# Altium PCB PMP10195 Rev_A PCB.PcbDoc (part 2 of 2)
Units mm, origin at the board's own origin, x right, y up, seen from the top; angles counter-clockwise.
Board outline 60.32 x 50 mm, 4 copper layers (Top Layer, Signal Layer 1, Signal Layer 2, Bottom Layer), stack 2.028 mm thick; 90 components, 50 nets, 184 pads, 78 vias.
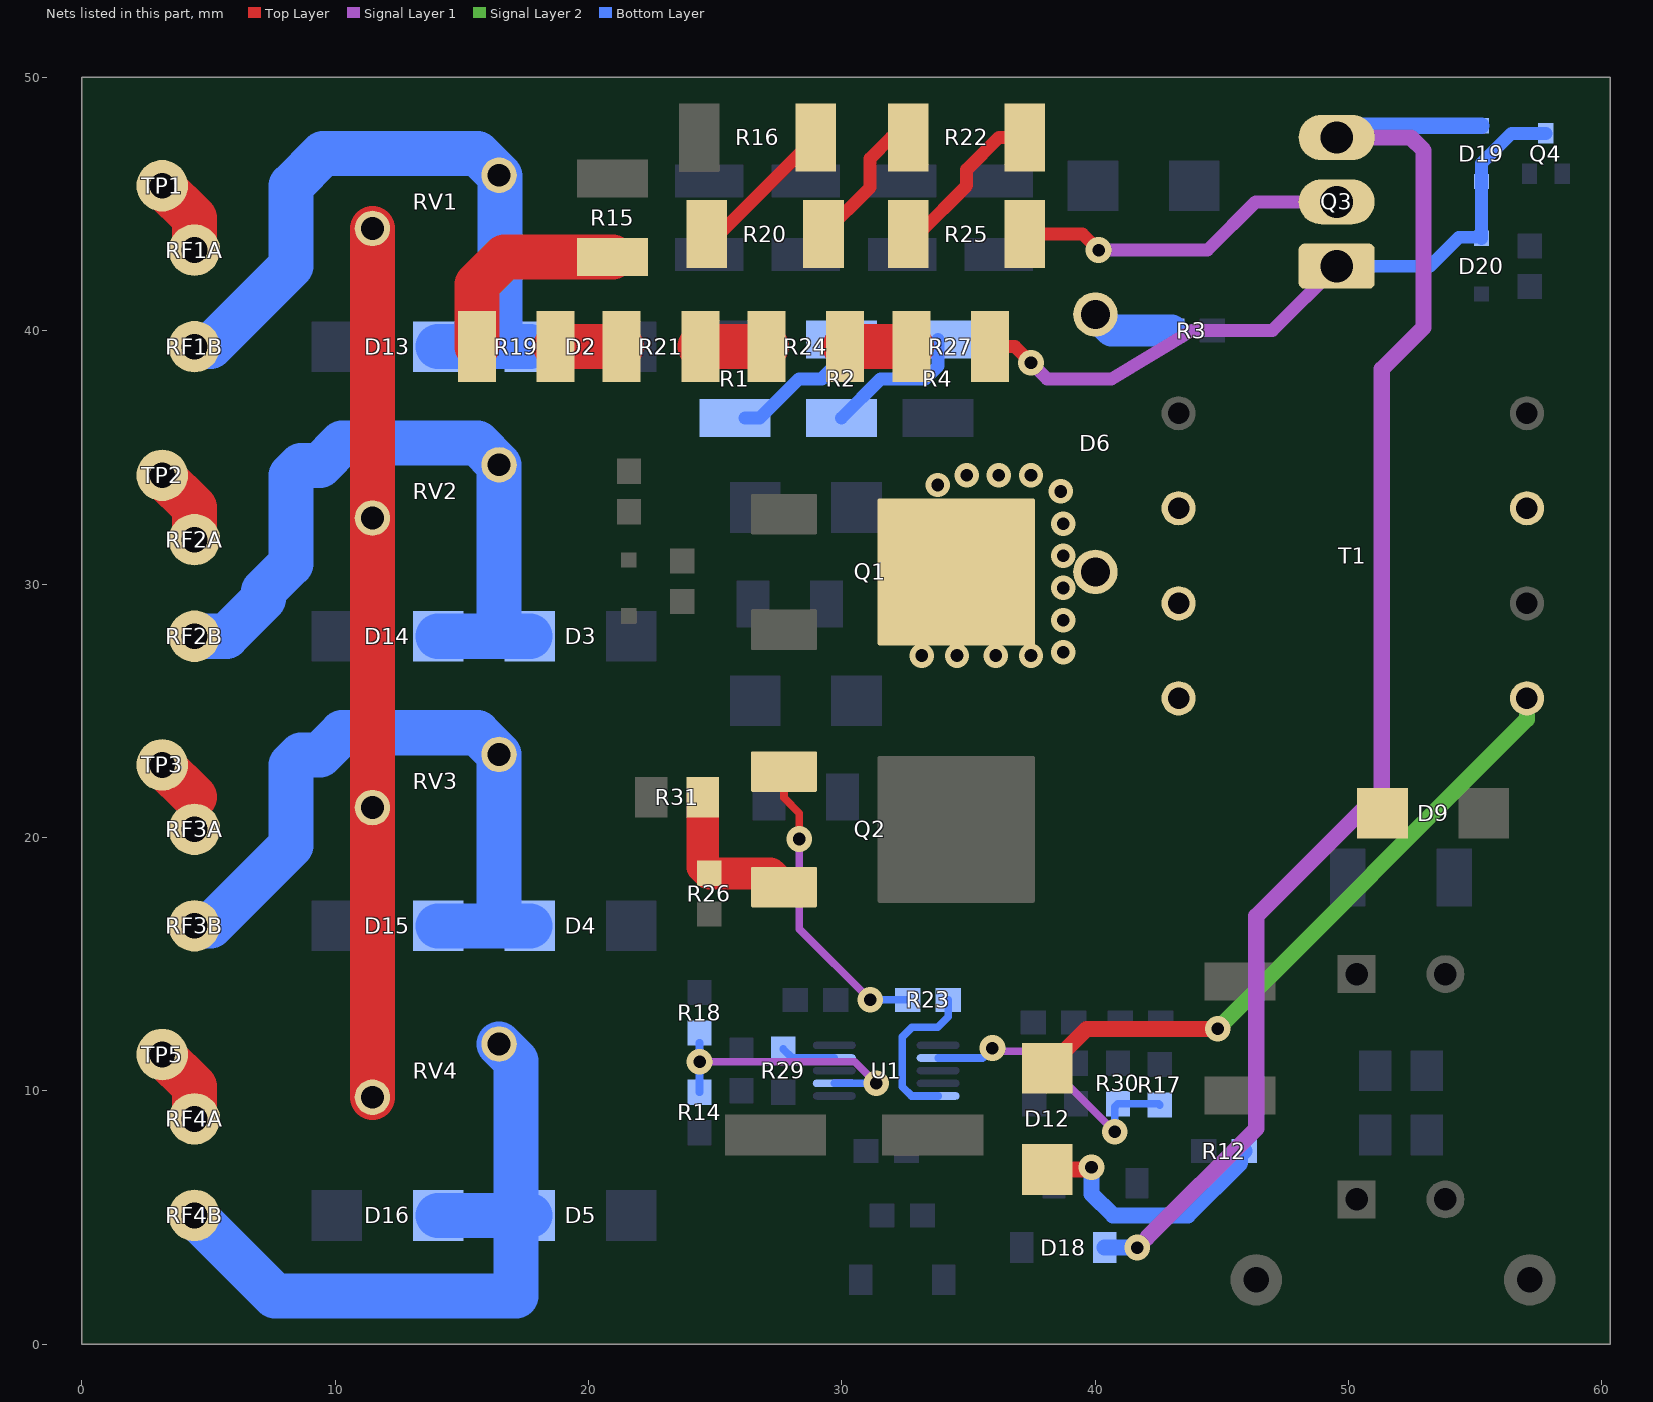
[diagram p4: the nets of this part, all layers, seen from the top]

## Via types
v1: diameter 0.965, hole 0.5, Top Layer to Bottom Layer, 51 vias
v2: diameter 1.016, hole 0.5, Top Layer to Bottom Layer, 19 vias
v3: diameter 1.27, hole 0.711, Top Layer to Bottom Layer, 8 vias

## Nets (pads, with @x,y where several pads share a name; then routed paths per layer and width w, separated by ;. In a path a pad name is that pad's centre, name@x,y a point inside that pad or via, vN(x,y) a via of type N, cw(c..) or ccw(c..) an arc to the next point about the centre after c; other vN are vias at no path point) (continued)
NetD2_2: D2.2 D13.1 RF1B.1 RV1.1 | length 27.8
  Bottom Layer w1.778: RF1B.1@4.445,39.37 5.08,39.37 8.255,42.545 8.255,45.72 9.525,46.99 15.615,46.99 RV1.1@16.47,46.135 16.51,46.095 16.51,39.37 ; D13.1@14.065,39.37 16.51,39.37 ; D2.2@17.685,39.37 16.51,39.37
NetD3_2: D3.2 D14.1 RF2B.1 RV2.1 | length 28.2
  Bottom Layer w1.778: RF2B.1@4.445,27.94 5.715,27.94 7.176,29.401 7.176,29.722 8.255,30.801 8.255,34.29 8.652,34.687 9.406,34.687 10.279,35.56 15.615,35.56 RV2.1@16.47,34.705 16.47,27.98 16.51,27.94 ; D14.1@14.065,27.94 16.51,27.94 ; D3.2@17.685,27.94 16.51,27.94
NetD4_2: D4.2 D15.1 RF3B.1 RV3.1 | length 27.8
  Bottom Layer w1.778: RF3B.1@4.445,16.51 5.08,16.51 8.255,19.685 8.255,22.86 8.652,23.257 9.406,23.257 10.279,24.13 15.615,24.13 RV3.1@16.47,23.275 16.47,16.55 16.51,16.51 ; D15.1@14.065,16.51 16.51,16.51 ; D4.2@17.685,16.51 16.51,16.51
NetD5_2: D5.2 D16.1 RF4B.1 RV4.1 | length 27.9
  Bottom Layer w1.778: RF4B.1@4.445,5.08 7.62,1.905 17.145,1.905 D5.2@17.145,5.08 ; D16.1@14.065,5.08 D5.2@17.145,5.08 ; RV4.1@16.47,11.845 17.145,11.17 D5.2@17.145,5.08 ; D5.2@17.685,5.08 D5.2@17.145,5.08
NetD6_1: D6.1 R3.1 | length 3.3
  Bottom Layer w1.27: D6.1@40.005,40.64 40.64,40.005 R3.1@43.015,40.005
NetD6_2: D6.2 Q1.4 T1.2 T1.3 T1.4
  other v1: 33.147,27.178 34.544,27.178 36.068,27.178 37.465,27.178 38.735,27.305 38.735,28.575 38.735,29.845 38.735,31.115 38.735,32.385 38.633,33.655 33.782,33.909 34.925,34.29 36.195,34.29 37.465,34.29
NetD9_2: D9.2 T1.7
NetD12_1: D12.1 R12.1 | length 10.5
  Top Layer w0.635: D12.1@38.1,6.89 39.755,6.89 v2(39.85,6.985)
  Bottom Layer w0.635: v2(39.85,6.985) 39.85,5.933 40.703,5.08 43.66,5.08 45.72,7.14 45.72,7.455 R12.1@45.885,7.62
NetD12_2: D12.2 T1.5 | length 25.5
  Top Layer w0.635: D12.2@38.1,10.89 39.656,12.446 v2(44.831,12.446)
  Signal Layer 2 w0.635: v2(44.831,12.446) 57.04,24.655 T1.5@57.04,25.49
NetD18_2: D18.2 D19.2 Q3.3 | length 58.3
  Signal Layer 1 w0.635: 42.037,4.191 46.355,8.509 46.355,16.891 51.308,21.844 51.308,38.481 52.959,40.132 52.959,47.117 52.451,47.625 Q3.3@49.53,47.625
  Bottom Layer w0.635: D18.2@40.372,3.81 v2(41.656,3.81) ; Q3.3@49.53,47.625 49.995,48.09 D19.2@55.245,48.09
NetD19_1: D19.1 D20.1 Q3.1 Q4.3 R27.1 | length 28
  Top Layer w0.508: R27.1@35.84,39.37 36.83,39.37 v2(37.465,38.735)
  Signal Layer 1 w0.508: v2(37.465,38.735) 38.1,38.1 40.64,38.1 43.815,40.005 46.99,40.005 Q3.1@49.53,42.545
  Bottom Layer w0.508: Q3.1@49.53,42.545 53.213,42.545 54.356,43.688 55.202,43.688 D20.1@55.245,43.645 D19.1@55.245,45.89 55.245,46.609 56.426,47.79 Q4.3@57.785,47.79
NetQ2_1: Q2.1 R23.2 | length 11.9
  Top Layer w0.305: Q2.1@27.715,22.6 27.715,21.561 28.321,20.955 v2(28.321,19.939)
  Signal Layer 1 w0.305: v2(28.321,19.939) 28.321,16.383 v2(31.115,13.589)
  Bottom Layer w0.305: v2(31.115,13.589) R23.2@32.601,13.589
NetQ2_3: Q2.3 R26.1 R31.2 | length 6.3
  Top Layer w1.27: R31.2@24.511,21.59 24.511,18.834 R26.1@24.765,18.58 27.175,18.58 Q2.3@27.715,18.04
NetQ3_2: Q3.2 R25.1 | length 13.4
  Top Layer w0.508: R25.1@37.225,43.815 39.497,43.815 v2(40.132,43.18)
  Signal Layer 1 w0.508: v2(40.132,43.18) 44.43,43.18 46.335,45.085 Q3.2@49.53,45.085
NetR1_1: R1.1 R2.2 | length 5.7
  Bottom Layer w0.508: R1.1@26.17,36.55 26.76,36.55 28.31,38.1 29.21,38.1 29.966,38.856 30.102,38.856 29.98,38.978 R2.2@29.98,39.65
NetR2_1: R2.1 R4.2 | length 5.7
  Bottom Layer w0.508: R2.1@29.98,36.55 31.53,38.1 33.29,38.1 33.79,38.6 R4.2@33.79,39.65
NetR14_1: R14.1 R18.2 U1.7 | length 10.9
  Signal Layer 1 w0.305: v2(24.384,11.15) 30.506,11.15 v2(31.361,10.295)
  Bottom Layer w0.305: R14.1@24.384,9.944 v2(24.384,11.15) R18.2@24.384,11.9 ; U1.7@29.7,10.295 v2(31.361,10.295)
NetR15_1: R15.1 R19.2 | length 8.3
  Top Layer w1.778: R19.2@15.595,39.37 15.595,41.818 16.678,42.9 R15.1@20.955,42.9
NetR16_1: R16.1 R20.2 | length 5.9
  Top Layer w0.508: R20.2@24.675,43.815 25.16,43.815 R16.1@28.97,47.625
NetR17_1: R17.1 R30.2 U1.2 | length 11.5
  Signal Layer 1 w0.305: v2(35.941,11.684) 35.941,11.557 37.592,11.557 v2(40.767,8.382)
  Bottom Layer w0.305: U1.2@33.8,11.295 35.552,11.295 35.814,11.557 35.941,11.557 v2(35.941,11.684) ; v2(40.767,8.382) 40.767,9.36 R30.2@40.894,9.487 42.496,9.487 R17.1@42.545,9.438
NetR19_1: R19.1 R21.2 | length 2.6
  Top Layer w1.778: R19.1@18.695,39.37 R21.2@21.31,39.37
NetR20_1: R20.1 R22.2 | length 5.6
  Top Layer w0.508: R20.1@29.275,43.815 31.115,45.655 31.115,46.8 31.94,47.625 R22.2@32.625,47.625
NetR21_1: R21.1 R24.2 | length 2.6
  Top Layer w1.778: R21.1@24.41,39.37 R24.2@27.025,39.37
NetR22_1: R22.1 R25.2 | length 6.6
  Top Layer w0.508: R25.2@32.625,43.815 33.02,43.815 34.925,45.72 34.925,46.355 36.195,47.625 R22.1@37.225,47.625
NetR23_1: R23.1 U1.5 | length 6.3
  Bottom Layer w0.305: U1.5@33.8,9.795 32.75,9.795 32.385,10.16 32.385,12.124 32.766,12.505 33.782,12.505 34.201,12.924 R23.1@34.201,13.589
NetR24_1: R24.1 R27.2 | length 2.6
  Top Layer w1.778: R24.1@30.125,39.37 R27.2@32.74,39.37
NetR29_2: R29.2 U1.9 | length 2.2
  Bottom Layer w0.305: R29.2@27.686,11.646 28.037,11.295 U1.9@29.7,11.295
NetRF1A_1: RF1A.1 TP1.1 | length 3.1
  Top Layer w1.778: TP1.1@3.175,45.72 4.445,44.45 RF1A.1@4.445,43.18
NetRF2A_1: RF2A.1 TP2.1 | length 3.1
  Top Layer w1.778: TP2.1@3.175,34.29 4.445,33.02 RF2A.1@4.445,31.75
NetRF3A_1: RF3A.1 TP3.1 | length 1.8
  Top Layer w1.778: TP3.1@3.175,22.86 4.445,21.59
NetRF4A_1: RF4A.1 TP5.1 | length 3.1
  Top Layer w1.778: TP5.1@3.175,11.43 4.445,10.16 RF4A.1@4.445,8.89
NetRV1_2: RV1.2 RV2.2 RV3.2 RV4.2 | length 34.3
  Top Layer w1.778: RV4.2@11.47,9.745 RV3.2@11.47,21.175 RV2.2@11.47,32.605 RV1.2@11.47,44.035

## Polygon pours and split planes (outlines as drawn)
GND on Top Layer "Signal Layer 1-No Net" (solid, remove dead copper, pour order 62): 14.665,26.64 15.24,27.215 15.24,27.305 24.765,27.305 24.765,26.035 26.035,24.765 27.94,24.765 28.791,23.914 28.842,23.914 28.956,23.8 29.21,23.546 29.21,15.24 29.845,14.605 29.966,14.484 30.087,14.605 41.91,14.605 42.328,14.187 42.545,14.187 42.545,1.27 41.91,0.635 14.605,0.635
GND on Top Layer "Top Layer-No Net 6" (solid, remove dead copper, pour order 56): 31.877,9.017 32.893,10.033 33.02,10.033 36.576,10.033 36.576,9.652 36.614,9.614 36.614,9.525 37.098,9.525 37.211,9.412 37.211,8.255 36.957,8.255 36.83,8.128 36.83,7.493 36.614,7.277 36.614,7.239 32.004,7.239 31.877,7.366 31.856,7.366
NetD6_2 on Top Layer "Top Layer-No Net" (solid, remove dead copper, pour order 61): 31.115,35.56 31.75,36.195 40.005,36.195 42.545,33.655 45.085,33.655 45.72,33.02 45.72,32.385 45.72,24.765 45.085,24.13 41.765,24.13 38.745,27.15 31.625,27.15 31.515,27.26 31.515,27.68 31.115,28.08 31.115,28.575
NetC12_2 on Top Layer "Top Layer-No Net 1" (solid, remove dead copper, pour order 60): 31.344,25.07 31.674,25.4 38.1,25.4 41.275,22.225 45.085,22.225 45.72,21.59 45.72,17.145 45.085,16.51 43.18,16.51 42.545,15.875 31.115,15.875
NetD9_2 on Top Layer "Top Layer-No Net 2" (solid, remove dead copper, pour order 57): 51.308,34.29 58.293,34.29 58.801,33.782 58.801,31.623 58.42,31.242 58.293,31.115 55.415,31.115 53.721,29.421 53.721,26.162 53.721,24.765 52.959,24.003 52.959,23.241 52.959,19.939 52.578,19.558 52.451,19.431 50.165,19.431 50.165,20.193 50.165,33.147
NetC8_1 on Top Layer "Top Layer-No Net 3" (solid, remove dead copper, pour order 59): 54.229,24.13 59.309,24.13 59.69,23.749 59.69,19.05 57.277,16.637 53.34,16.637 52.324,15.621 52.324,14.097 51.181,12.954 45.847,12.954 45.466,13.335 44.45,13.335 44.196,13.589 44.196,15.113 46.863,15.113 48.006,16.256 48.006,17.907 48.768,18.669 49.149,19.05 53.34,19.05 53.683,19.05 54.102,19.469
NetC7_1 on Top Layer "Top Layer-No Net 4" (solid, remove dead copper, pour order 58): 44.45,11.303 50.292,11.303 51.816,9.779 51.816,3.048 49.784,1.016 45.212,1.016 44.831,1.397 44.831,1.524 44.45,1.905
NetC12_2 on Bottom Layer "Cooling C12_2 Bottom" (solid, pour order 54): 31.344,25.07 31.674,25.4 38.1,25.4 41.275,22.225 45.085,22.225 45.72,21.59 45.72,17.145 45.085,16.51 43.18,16.51 42.545,15.875 31.115,15.875
NetD6_2 on Bottom Layer "Cooling D6_2 Bottom" (solid, remove dead copper, pour order 55): 31.115,35.55 31.75,36.185 40.005,36.185 42.545,33.645 45.085,33.645 45.72,33.01 45.72,32.375 45.72,24.755 45.085,24.12 41.765,24.12 39.215,26.67 32.095,26.67 31.515,27.25 31.515,27.67 31.115,28.07 31.115,28.565
GND on Bottom Layer "Bottom Layer-No Net 2" (solid, remove dead copper, pour order 65): 24.13,26.67 27.94,26.67 28.575,26.035 28.575,15.24 42.545,15.24 43.655,14.13 43.815,14.13 43.617,13.932 43.617,1.707 42.545,0.635 24.13,0.635
NetC7_1 on Bottom Layer "Bottom Layer-No Net" (solid, remove dead copper, pour order 64): 48.26,11.938 51.651,11.938 52.07,11.519 52.07,4.826 51.181,3.937 48.006,3.937 47.879,4.064 47.879,11.557 48.133,11.811
GND-S on Bottom Layer "Bottom Layer-No Net 1" (solid, remove dead copper, pour order 66): 49.804,39.029 59.049,39.029 59.329,38.749 59.329,1.284 58.694,0.649 54.249,0.649 52.344,2.554 52.344,12.714 52.34,16.497 52.344,16.524 52.335,21.59 48,22.688 48,37.824 49.025,38.459
GND on Signal Layer 2 "Top Layer-No Net 5" (solid, remove dead copper, pour order 63): 0.635,48.895 1.27,49.53 59.055,49.53 59.69,48.895 59.69,28.898 58.097,27.305 43.815,13.023 43.815,1.905 42.545,0.635 1.27,0.635 0.635,1.27

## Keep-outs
Keep-Out Layer:
  text ".Layer_Name" at 14.656,-21.806 h1.52

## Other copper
Top Layer:
  text ".Layer_Name" at 14.656,-21.806 h1.52
Signal Layer 2:
  pour cut-out: 31.175,25.4 38.1,25.4 41.346,22.154 45.156,22.154 45.72,21.59 45.72,17.78 43.815,15.875 31.301,15.875 31.12,16.057
  pour cut-out: 31.115,35.56 31.75,36.195 42.515,36.195 45.72,32.99 45.72,24.765 45.085,24.13 41.765,24.13 38.745,27.15 31.625,27.15 31.625,27.57 31.115,28.08
Bottom Layer:
  text ".Layer_Name" at 14.656,-21.806 h1.52

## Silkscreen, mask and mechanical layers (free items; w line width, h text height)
Top Overlay:
  text ".PRJ_Number" at 6.731,2.032 h1.52
  text ".PCB_Rev" at 20.904,1.981 h1.52
  text "-" at 18.999,1.854 h1.52
  text ".Layer_Name" at 14.656,-21.806 h1.52
Bottom Overlay:
  text ".Layer_Name" at 14.656,-21.806 h1.52
Top Paste:
  text ".Layer_Name" at 14.656,-21.806 h1.52
Bottom Paste:
  text ".Layer_Name" at 14.656,-21.806 h1.52
Top Solder:
  text ".Layer_Name" at 14.656,-21.806 h1.52
  text ".Layer_Name" at 14.656,-21.806 h1.52
Bottom Solder:
  text ".Layer_Name" at 14.656,-21.806 h1.52
Drill Guide:
  text ".Layer_Name" at 14.656,-21.806 h1.52
M1 Board Outline:
  the board outline again, w0.3
  text ".Layer_Name" at 30.302,-21.946 h1.52
M2 Board Dimensions:
  rectangle: 0,-6.985 3.175,-3.81
  rectangle: 3.175,-10.16 12.7,-6.985
  lines w0.178: 0,-6.985 25.4,-6.985 ; 3.175,-10.16 3.175,-3.81 ; 6.35,-10.16 6.35,-3.81 ; 12.7,-10.16 12.7,-3.81 ; 19.05,-10.16 19.05,-3.81 ; 0,-10.16 25.4,-10.16 25.4,-3.81 0,-3.81 0,-10.16
  text ".Layer_Name" at -6.655,-21.768 h1.52
M3 3D STEP Top:
  text ".Layer_Name" at 14.656,-21.806 h1.52
M4 3D STEP Bottom:
  text ".Layer_Name" at 14.656,-21.806 h1.52
M5 Assembly Top:
  circle w0.254: c4.442,5.076 r2.837
  circle w0.254: c4.442,16.506 r2.837
  circle w0.254: c4.442,27.936 r2.837
  circle w0.254: c4.442,39.366 r2.837
  lines w0.254: -7.417,-23.626 160.223,-23.626 ; -7.417,-18.462 160.274,-18.462 ; -7.417,-13.297 -7.417,-28.791 94.31,-28.791 160.274,-28.791 160.274,-13.297 -7.404,-13.297 -7.404,-28.791 32.614,-28.791 ; 55.194,-28.791 55.194,-13.297 ; 87.376,-18.462 87.376,-13.297 ; 108.712,-18.462 108.712,-13.297 ; 124.511,-28.956 124.511,-23.804 ; 3.937,4.826 4.953,4.826 4.953,9.398 3.937,9.398 3.937,4.826 ; 3.937,16.256 4.953,16.256 4.953,20.828 3.937,20.828 3.937,16.256 ; 3.937,27.686 4.953,27.686 4.953,32.258 3.937,32.258 3.937,27.686 ; 3.937,39.116 3.937,43.688 4.953,43.688 4.953,39.116 3.937,39.116
  text ".PRJ_Number" at 8.763,4.293 h1.52
  text ".PCB_Rev" at 22.708,4.293 h1.52
  text "-" at 20.65,4.242 h1.52
  text "PMP10195 Rev_E Board has been" at 64.897,2.642 h1.5
  text "built on PMP10195 Rev_A PWB" at 64.745,-0.889 h1.5
  text "COMPONENTS MARKED 'DNP' SHOULD NOT BE POPULATED." at 29.299,-8.09 h1.52
  text "ASSEMBLY VARIANT:" at 29.286,-11.024 h1.52
  text ".VariantName" at 55.601,-11.024 h1.52
  text "PCB VIEWED FROM TOP SIDE" at -5.804,-16.654 h1.52
  text "BOARD #:" at 57.099,-16.654 h1.52
  text ".PRJ_Number" at 70.955,-16.654 h1.52
  text "REV:" at 92.405,-16.654 h1.52
  text ".PCB_Rev" at 99.809,-16.654 h1.52
  text "SVN REV:" at 113.69,-16.654 h1.52
  text ".VersionControl_RevNumber" at 126.543,-16.654 h1.52
  text "TID #:" at 57.099,-21.819 h1.52
  text ".TID" at 70.955,-21.819 h1.52
  text "PLOT NAME =" at -5.804,-27.034 h1.52
  text ".plot_File_Name" at 14.656,-27.034 h1.52
  text "GENERATED    :" at 57.15,-27.034 h1.52
  text ".Print_Date" at 79.235,-27.034 h1.52
  text ".Print_Time" at 97.752,-27.034 h1.52
  text "TEXAS INSTRUMENTS" at 129.87,-27.034 h1.52
M6 Assembly Bottom:
  lines w0.254: -7.429,-18.474 160.261,-18.474 ; -7.379,-23.639 160.261,-23.639 ; 28.334,-28.969 28.334,-23.817 ; 44.133,-18.474 44.133,-13.31 ; 65.468,-18.474 65.468,-13.31 ; 97.65,-28.804 97.65,-13.31 ; 120.231,-28.804 160.249,-28.804 160.249,-13.31 -7.429,-13.31 -7.429,-28.804 58.534,-28.804 160.261,-28.804 160.261,-13.31
  text "COMPONENTS MARKED 'DNP' SHOULD NOT BE POPULATED." at 154.991,-8.077 h1.52
  text ".VariantName" at 128.473,-11.024 h1.52
  text "ASSEMBLY VARIANT:" at 154.864,-11.024 h1.52
  text ".VersionControl_RevNumber" at 26.302,-16.667 h1.52
  text "SVN REV:" at 39.154,-16.667 h1.52
  text ".PCB_Rev" at 53.035,-16.667 h1.52
  text "REV:" at 60.439,-16.667 h1.52
  text ".PRJ_Number" at 81.89,-16.667 h1.52
  text "BOARD #:" at 95.745,-16.667 h1.52
  text "PCB VIEWED FROM BOTTOM SIDE" at 158.648,-16.667 h1.52
  text ".TID" at 81.89,-21.831 h1.52
  text "TID #:" at 95.745,-21.831 h1.52
  text "TEXAS INSTRUMENTS" at 22.974,-27.047 h1.52
  text ".Print_Time" at 55.093,-27.047 h1.52
  text ".Print_Date" at 73.609,-27.047 h1.52
  text "GENERATED    :" at 95.694,-27.047 h1.52
  text ".plot_File_Name" at 138.189,-27.047 h1.52
  text "PLOT NAME =" at 158.648,-27.047 h1.52
M9 Title Sheet:
  drawing of 57 lines, arcs and shapes, not listed
  text "1" at 18.792,204.127 h1.78
  text "2" at 82.182,204.127 h1.78
  text "3" at 145.411,204.127 h1.78
  text "4" at 209.08,204.127 h1.78
  text "5" at 272.555,204.127 h1.78
  text "6" at 336.182,204.127 h1.78
  text "A" at -10.579,175.095 h1.78
  text "A" at 365.341,175.095 h1.78
  text "B" at -10.579,114.643 h1.78
  text "B" at 365.341,114.643 h1.78
  text "C" at -10.579,54.318 h1.78
  text "C" at 365.341,54.318 h1.78
  text "PROJECT TITLE:" at 288.125,7.048 h1.14
  text ".PRJ_Title" at 289.395,3.662 h1.78
  text "DESIGNED FOR:" at 288.125,-0.597 h1.14
  text ".PRJ_Customer" at 289.395,-4.153 h1.78
  text "D" at -10.579,-5.88 h1.78
  text "D" at 365.341,-5.88 h1.78
  text "FILE NAME:" at 288.125,-8.217 h1.14
  text ".PCB_File_Name_No_Path" at 289.395,-11.265 h1.78
  text "Texas Instruments (TI) and/or its licensors do not warrant the accuracy or completeness of this specification" at 161.9,-15.376 h1.14
  text "ENGINEER:" at 288.125,-15.583 h1.14
  text "LAYOUT BY:" at 326.352,-15.583 h1.14
  text "or any information contained therein. TI and/or its licensors do not warrant that this design will meet" at 160.757,-18.237 h1.14
  text ".PRJ_Engineer" at 289.395,-19.52 h1.78
  text ".PCB_Layout" at 327.635,-19.52 h1.78
  text "the specifications, will be suitable for your application or fit for any particular purpose, or will operate in" at 160.757,-21.099 h1.14
  text ".Layer_Name" at 14.656,-21.806 h1.52
  text "ALTIUM DESIGNER VERSION:" at 326.352,-23.457 h1.14
  text "an implementation. TI and/or its licensors do not warrant that the design is production worthy. You should" at 160.757,-23.961 h1.14
  text "completely validate and test your design implementation to confirm the system functionality for your application." at 161.9,-26.822 h1.14
  text ".print_Scale" at 289.395,-26.843 h1.78
  text ".Application_BuildNumber" at 327.635,-26.843 h1.78
  text "1" at 18.792,-32.093 h1.78
  text "2" at 82.182,-32.093 h1.78
  text "3" at 145.411,-32.093 h1.78
  text "4" at 209.08,-32.093 h1.78
  text "5" at 272.555,-32.093 h1.78
  text "6" at 336.182,-32.093 h1.78
M10 Fab Notes:
  drawing of 189 lines, arcs and shapes, not listed
  text "DESIGN INFORMATION" at 314.478,153.111 h1.52
  text "MIN. TRACK WIDTH:" at 298.106,148.539 h1.52
  text "8" at 325.951,148.539 h1.52
  text "MIL" at 329.881,148.539 h1.52
  text "MIN. CLEARANCE:" at 298.106,145.186 h1.52
  text "0.2" at 324.427,145.186 h1.52
  text "mm" at 329.881,145.186 h1.52
  text "MIN. VIA PAD SIZE:" at 298.106,141.834 h1.52
  text "24" at 325.189,141.834 h1.52
  text "MIL" at 329.881,141.834 h1.52
  text "0.05mm (2MIL)" at 315.759,138.234 h1.52
  text "MINIMUM ANNULAR RING" at 289.744,138.125 h1.52
  text "EXTERNAL" at 333.742,138.125 h1.52
  text "PER" at 294.824,135.128 h1.52
  text "IPC-D-275 CLASS 2 LEVEL C" at 300.412,135.128 h1.52
  text "MIL, HOLES" at 338.213,132.276 h1.52
  text "+/-" at 328.244,132.258 h1.52
  text "+/-" at 349.936,132.258 h1.52
  text "REGISTRATION TOLERANCES:" at 289.744,132.131 h1.52
  text "METAL" at 320.218,132.131 h1.52
  text "5" at 334.853,132.131 h1.52
  text "3" at 356.012,132.131 h1.52
  text "MIL" at 358.964,132.131 h1.52
  text "+/-" at 349.936,129.261 h1.52
  text "HOLE SIZE TOLERANCE (UNLESS OTHERWISE SPECIFIED):" at 289.744,129.134 h1.52
  text "3" at 356.012,129.134 h1.52
  text "MIL" at 358.964,129.134 h1.52
  text "MATERIAL:" at 287.844,123.813 h1.52
  text "FR-4 High Tg" at 312.9,120.249 h1.52
  text "FR-408" at 298.538,120.031 h1.52
  text "OTHER" at 336.333,120.031 h1.52
  text "X" at 308.966,119.939 h1.52
  text "62 MIL (1.6mm) +/-10%" at 306.668,115.898 h1.52
  text "THICKNESS:" at 289.744,115.789 h1.52
  text "X" at 303.413,115.789 h1.52
  text "OTHER" at 339.305,115.789 h1.52
  text "TOLERANCE:" at 289.744,111.776 h1.52
  text "X" at 311.062,111.776 h1.52
  text "ANSI IPC-6012 TYPE 3 CLASS 2" at 315.81,111.776 h1.52
  text "OTHER +/-" at 315.81,107.814 h1.52
  text "BOW & TWIST:" at 289.744,103.826 h1.52
  text "X" at 311.062,103.826 h1.52
  text "ANSI IPC-6012 TYPE 3 CLASS 2" at 315.81,103.826 h1.52
  text "OTHER +/-" at 315.81,99.8 h1.52
  text "DRILLING:" at 287.844,96.282 h1.52
  text "REFERENCE:" at 289.744,93.31 h1.52
  text "X" at 306.209,93.31 h1.52
  text "AS SHOWN" at 310.958,93.31 h1.52
  text "X" at 329.094,93.31 h1.52
  text "NC_DRILL FILES" at 332.574,93.31 h1.52
  text "PTH MIN COPPER THICKNESS:" at 289.744,89.297 h1.52
  text "X" at 324.039,89.297 h1.52
  text "1MIL" at 327.519,89.297 h1.52
  text "OTHER" at 340.143,89.297 h1.52
  text "BOARD FINISH:" at 287.844,85.259 h1.52
  text "SILKSCREEN:" at 291.787,82.261 h1.52
  text "X" at 315.886,82.261 h1.52
  text "TOP" at 319.086,82.261 h1.52
  text "X" at 328.84,82.261 h1.52
  text "BOTTOM" at 332.066,82.261 h1.52
  text "SILKSCREEN COLOR:" at 291.787,78.02 h1.52
  text "X" at 315.86,78.02 h1.52
  text "WHITE" at 319.086,78.02 h1.52
  text "OTHER" at 332.066,78.02 h1.52
  text "X" at 319.187,73.976 h1.52
  text "GREEN" at 322.414,73.976 h1.52
  text "OTHER" at 338.111,73.976 h1.52
  text "SOLDER RESIST COLOR:" at 291.787,73.702 h1.52
  text "X" at 319.187,69.658 h1.52
  text "MATTE" at 322.414,69.658 h1.52
  text "SEMI-GLOSS" at 338.099,69.642 h1.52
  text "IMMERSION GOLD (ENIG)" at 314.794,64.87 h1.52
  text "ENEPIG" at 348.767,64.786 h1.52
  text "SURFACE FINISH:" at 287.844,64.761 h1.52
  text "X" at 310.045,64.761 h1.52
  text "IMM. TIN/SILVER OR EQUIV" at 296.215,60.773 h1.52
  text "OTHER" at 332.574,60.773 h1.52
  text "ARRAY/PANEL:" at 287.844,56.226 h1.52
  text "CUT AND TRIM PER M1 BOARD OUTLINE" at 314.794,56.118 h1.52
  text "N.C. ROUTE" at 314.794,52.264 h1.52
  text "X" at 332.04,52.264 h1.52
  text "V. SCORE" at 336.79,52.264 h1.52
  text "CERTIFICATION:" at 287.844,48.784 h1.52
  text "MATERIALS AND WORKMANSHIP FOR ALL PCBS" at 306.259,48.784 h1.52
  text "TO MEET OR EXCEED THE REQUIREMENTS OF:" at 306.259,46.295 h1.52
  text "X" at 296.773,42.828 h1.52
  text "ANSI IPC-A-600F CLASS ->" at 300.303,42.828 h1.52
  text "X" at 341.935,42.828 h1.52
  text "2" at 344.956,42.828 h1.52
  text "1" at 336.955,42.79 h1.52
  text "3" at 353.948,42.79 h1.52
  text "X" at 296.825,38.777 h1.52
  text "UL 94V-0" at 300.303,38.777 h1.52
  text "X" at 317.45,38.777 h1.52
  text "RoHS" at 320.928,38.777 h1.52
  text "OTHER" at 337.296,38.777 h1.52
  text "PER ORDER" at 347.381,38.777 h1.52
  text "ADDITIONAL REQUIREMENTS:" at 287.844,35.195 h1.52
  text "MICROSECTION:" at 289.744,32.274 h1.52
  text "YES" at 312.749,32.274 h1.52
  text "REQUIRED" at 334.631,28.308 h1.52
  text "BARE BOARD ELEC. TEST:" at 289.744,28.236 h1.52
  text "NONE" at 322.909,28.236 h1.52
  text "X" at 331.405,28.236 h1.52
  text "PER ORDER" at 349.668,28.236 h1.52
  text "MANUFACTURER'S UL:" at 289.744,24.248 h1.52
  text "RAIL" at 319.353,24.139 h1.52
  text "METAL" at 331.845,24.139 h1.52
  text "X" at 341.376,24.13 h1.52
  text "SILK" at 344.842,24.139 h1.52
  text ".Layer_Name" at 14.656,-21.806 h1.52
M11 Gerber Information:
  lines w0.254: -7.417,-23.626 160.223,-23.626 ; -7.417,-18.462 160.274,-18.462 ; -7.417,-13.297 -7.417,-28.791 94.31,-28.791 160.274,-28.791 160.274,-13.297 -7.404,-13.297 -7.404,-28.791 32.614,-28.791 ; 55.194,-28.791 55.194,-13.297 ; 87.376,-18.462 87.376,-13.297 ; 108.712,-18.462 108.712,-13.297 ; 124.511,-28.956 124.511,-23.804
  text "ALL ARTWORK VIEWED FROM TOP SIDE" at -5.804,-16.654 h1.52
  text "BOARD #:" at 57.099,-16.654 h1.52
  text ".PRJ_Number" at 70.955,-16.654 h1.52
  text "REV:" at 92.405,-16.654 h1.52
  text ".PCB_Rev" at 99.809,-16.654 h1.52
  text "SVN REV:" at 113.69,-16.654 h1.52
  text ".VersionControl_RevNumber" at 126.543,-16.654 h1.52
  text "LAYER NAME =" at -5.804,-21.806 h1.52
  text "TID #:" at 57.099,-21.819 h1.52
  text ".TID" at 70.955,-21.819 h1.52
  text "PLOT NAME =" at -5.804,-27.034 h1.52
  text ".plot_File_Name" at 14.656,-27.034 h1.52
  text "GENERATED    :" at 57.15,-27.034 h1.52
  text ".Print_Date" at 79.235,-27.034 h1.52
  text ".Print_Time" at 97.752,-27.034 h1.52
  text "TEXAS INSTRUMENTS" at 129.87,-27.034 h1.52
M12 Stackup:
  drawing of 191 lines, arcs and shapes, not listed
  text "Layer" at 248.675,198.882 h1.52
  text "Name" at 259.086,198.882 h1.52
  text "Material" at 282.702,198.882 h1.52
  text "Thickness" at 304.54,198.882 h1.52
  text "Constant" at 321.046,198.882 h1.52
  text "Board Layer Stack" at 335.52,198.882 h1.52
  text "1" at 248.675,195.834 h1.52
  text "Top Overlay" at 259.086,195.834 h1.52
  text "2" at 248.675,192.786 h1.52
  text "Top Solder" at 259.086,192.786 h1.52
  text "Solder Resist" at 282.702,192.786 h1.52
  text "0.40mil" at 304.54,192.786 h1.52
  text "3.5" at 321.046,192.786 h1.52
  text "3" at 248.675,189.738 h1.52
  text "Top Layer" at 259.086,189.738 h1.52
  text "Copper" at 282.702,189.738 h1.52
  text "1.40mil" at 304.54,189.738 h1.52
  text "4" at 248.675,186.69 h1.52
  text "Dielectric1" at 259.086,186.69 h1.52
  text "FR-4" at 282.702,186.69 h1.52
  text "59.20mil" at 304.54,186.69 h1.52
  text "4.8" at 321.046,186.69 h1.52
  text "5" at 248.675,183.642 h1.52
  text "Bottom Layer" at 259.086,183.642 h1.52
  text "Copper" at 282.702,183.642 h1.52
  text "1.40mil" at 304.54,183.642 h1.52
  text "6" at 248.675,180.594 h1.52
  text "Bottom Solder" at 259.086,180.594 h1.52
  text "Solder Resist" at 282.702,180.594 h1.52
  text "0.40mil" at 304.54,180.594 h1.52
  text "3.5" at 321.046,180.594 h1.52
  text "7" at 248.675,177.546 h1.52
  text "Bottom Overlay" at 259.086,177.546 h1.52
  text ".Layer_Name" at 14.656,-21.806 h1.52
M13 Component Bodies Top:
  text ".Layer_Name" at 14.656,-21.806 h1.52
M14 Component Bodies Bottom:
  text ".Layer_Name" at 14.656,-21.806 h1.52
M15 Courtyards Top:
  text ".Layer_Name" at 14.656,-21.806 h1.52
M16 Courtyards Bottom:
  text ".Layer_Name" at 14.656,-21.806 h1.52
Drill Drawing:
  circle w0.254: c144.597,81.809 r0.38
  circle w0.254: c144.597,81.809 r0.633
  circle w0.254: c144.597,70.42 r0.633
  lines w0.254: 143.964,54.603 144.597,54.919 145.23,54.603 144.913,55.235 145.23,55.868 144.597,55.552 143.964,55.868 144.281,55.235 143.964,54.603 ; 143.964,58.399 145.23,58.399 145.23,59.664 143.964,59.664 143.964,58.399 ; 143.964,63.461 145.23,63.461 144.597,62.195 143.964,63.461 ; 143.964,66.624 144.597,65.991 145.23,66.624 144.597,67.257 143.964,66.624 ; 143.964,73.584 143.964,73.9 144.281,74.217 143.964,74.533 143.964,74.849 144.281,74.849 144.597,74.533 144.913,74.849 145.23,74.849 145.23,74.533 144.913,74.217 145.23,73.9 145.23,73.584 144.913,73.584 144.597,73.9 144.281,73.584 143.964,73.584 ; 143.964,77.38 145.23,77.38 145.23,78.646 143.964,78.646 143.964,77.38 ; 144.217,77.633 144.977,77.633 144.977,78.392 144.217,78.392 144.217,77.633
  lines w0.305: 142.24,53.464 196.073,53.464 ; 142.24,83.834 196.073,83.834 ; 151.655,49.667 151.655,87.63 ; 160.726,49.667 160.726,87.63 ; 177.541,49.667 177.541,87.63 ; 184.763,49.667 184.763,87.63 ; 142.24,49.667 196.073,49.667 196.073,87.63 142.24,87.63 142.24,49.667
  text "Symbol" at 144.518,84.973 h1.83
  text "Quantity" at 152.794,84.973 h1.83
  text "Finished Hole Size" at 161.865,84.973 h1.83
  text "Plated" at 178.679,84.973 h1.83
  text "Hole Type" at 185.902,84.973 h1.83
  text "70" at 152.794,81.176 h1.52
  text "19,70mil (0,500mm)" at 161.865,81.176 h1.52
  text "PTH" at 178.679,81.176 h1.52
  text "Round" at 185.902,81.176 h1.52
  text "8" at 152.794,77.38 h1.52
  text "28,00mil (0,711mm)" at 161.865,77.38 h1.52
  text "PTH" at 178.679,77.38 h1.52
  text "Round" at 185.902,77.38 h1.52
  text "8" at 152.794,73.584 h1.52
  text "33,46mil (0,850mm)" at 161.865,73.584 h1.52
  text "PTH" at 178.679,73.584 h1.52
  text "Round" at 185.902,73.584 h1.52
  text "4" at 152.794,69.788 h1.52
  text "35,00mil (0,889mm)" at 161.865,69.788 h1.52
  text "PTH" at 178.679,69.788 h1.52
  text "Round" at 185.902,69.788 h1.52
  text "8" at 152.794,65.991 h1.52
  text "35,43mil (0,900mm)" at 161.865,65.991 h1.52
  text "PTH" at 178.679,65.991 h1.52
  text "Round" at 185.902,65.991 h1.52
  text "14" at 152.794,62.195 h1.52
  text "40,00mil (1,016mm)" at 161.865,62.195 h1.52
  text "PTH" at 178.679,62.195 h1.52
  text "Round" at 185.902,62.195 h1.52
  text "2" at 152.794,58.399 h1.52
  text "45,28mil (1,150mm)" at 161.865,58.399 h1.52
  text "PTH" at 178.679,58.399 h1.52
  text "Round" at 185.902,58.399 h1.52
  text "3" at 152.794,54.603 h1.52
  text "50,00mil (1,270mm)" at 161.865,54.603 h1.52
  text "PTH" at 178.679,54.603 h1.52
  text "Round" at 185.902,54.603 h1.52
  text "117 Total" at 152.794,50.806 h1.52
  text ".Layer_Name" at 14.656,-21.806 h1.52

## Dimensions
0,-10.16 to 25.4,-10.16 on M2 Board Dimensions
0,0 to 0,50 on M2 Board Dimensions
0,0 to 60.325,0 on M2 Board Dimensions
